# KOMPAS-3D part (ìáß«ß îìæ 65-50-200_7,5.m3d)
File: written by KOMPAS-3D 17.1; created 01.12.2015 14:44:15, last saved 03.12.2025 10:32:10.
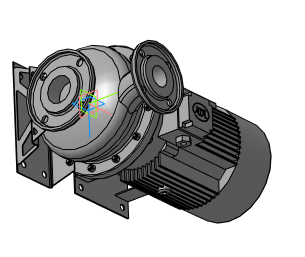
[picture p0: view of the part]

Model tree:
1. Операция без истории:3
